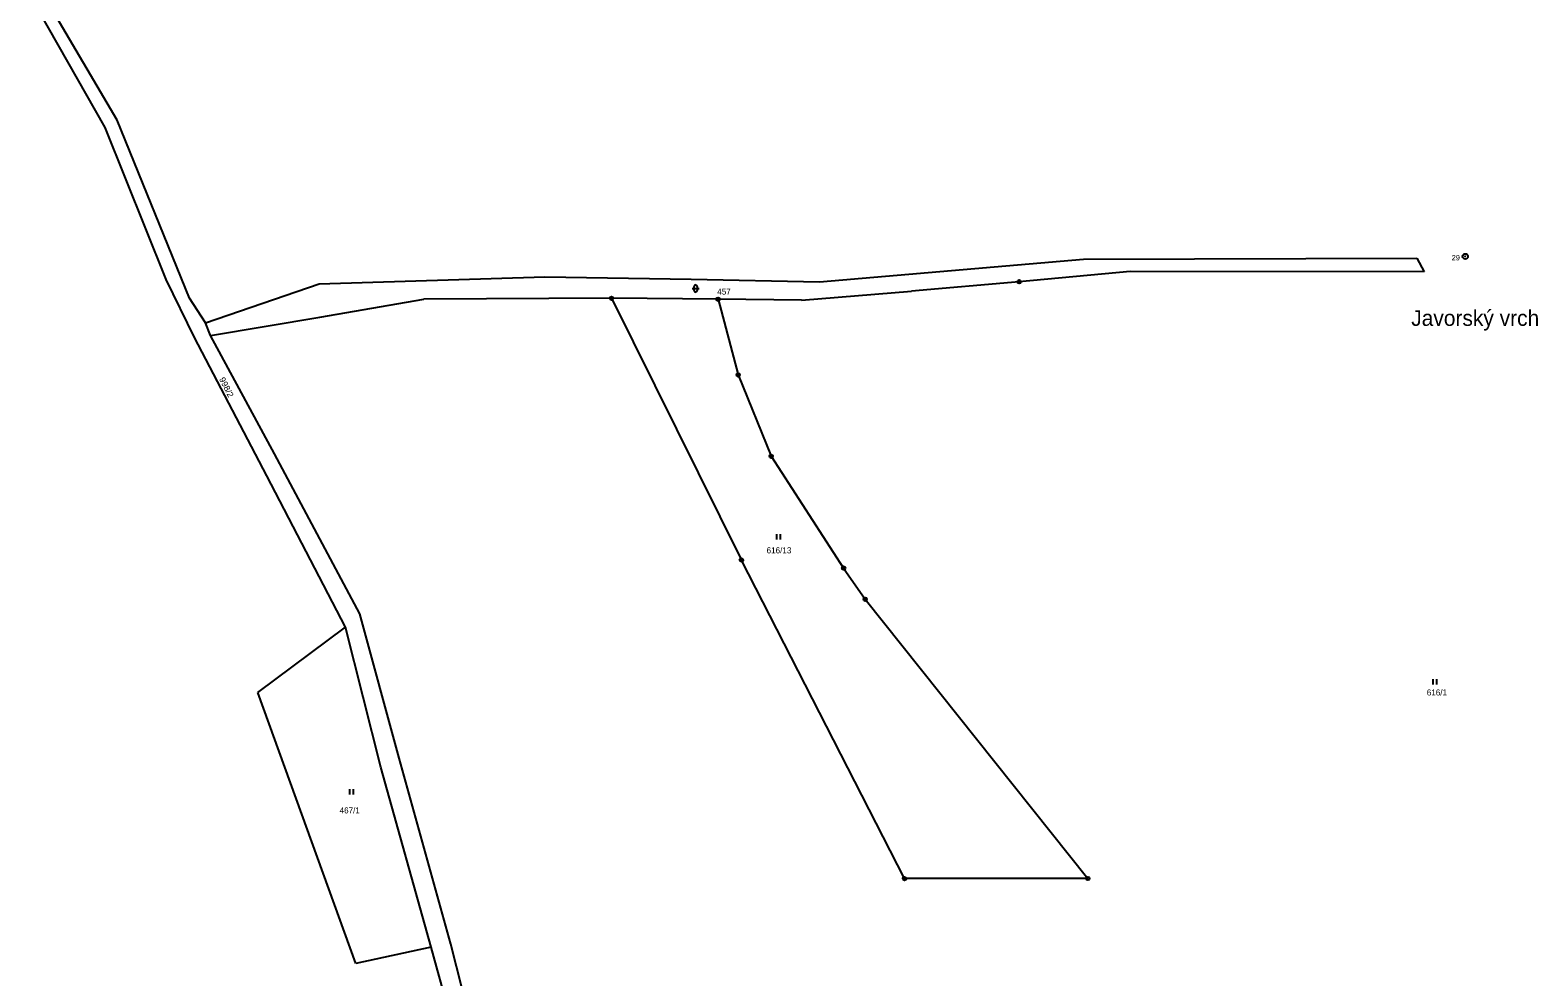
# Model space of a CAD drawing. Extents: x -754970 to -752637, y -970569 to -968179.
# Drawn here: x -754897.5 to -754473.8, y -969234.1 to -968968.3 of the extents above; entities that cross this region are included whole.
import ezdxf
from ezdxf.enums import TextEntityAlignment as Align

# ---------------------------------------------------------------- set-up
doc = ezdxf.new("R2010")
doc.units = 0
doc.header["$LTSCALE"] = 0.68
for name, color, linetype, lineweight in [('1', 7, 'Continuous', 25), ('3', 7, 'Continuous', 25), ('7', 7, 'Continuous', 13), ('8', 7, 'Continuous', 25)]:
    doc.layers.add(name, color=color, linetype=linetype, lineweight=lineweight)
doc.layers.add('2', color=7, linetype='Continuous')

msp = doc.modelspace()

# ---------------------------------------------------------------- linework, layer by layer
at = {"layer": '1'}
for p, q in [((-754876.46, -968995.58), (-754897.5, -968958.43)), ((-754873.07, -968993.57), (-754892.08, -968961.21)), ((-754852.68, -969043.52), (-754873.07, -968993.57)), ((-754859.28, -969038.29), (-754876.46, -968995.58)), ((-754601.47, -969032.61), (-754507.79, -969032.31)), ((-754507.79, -969032.31), (-754505.73, -969036.16)), ((-754675.7, -969038.93), (-754601.47, -969032.61)), ((-754588.39, -969035.99), (-754619.57, -969038.92)), ((-754505.73, -969036.16), (-754588.39, -969035.99)), ((-754851.31, -969054.58), (-754859.28, -969038.29)), ((-754848.25, -969050.43), (-754816.28, -969039.5)), ((-754816.28, -969039.5), (-754752.89, -969037.51)), ((-754752.89, -969037.51), (-754711.78, -969038.17)), ((-754711.78, -969038.17), (-754675.7, -969038.93)), ((-754619.57, -969038.92), (-754649.88, -969041.54)), ((-754848.25, -969050.43), (-754852.68, -969043.52)), ((-754816.13, -969048.84), (-754786.87, -969043.85)), ((-754734.15, -969043.55), (-754786.87, -969043.85)), ((-754734.15, -969043.55), (-754697.63, -969117.06)), ((-754704.19, -969043.83), (-754734.15, -969043.55)), ((-754704.19, -969043.83), (-754698.54, -969065.07)), ((-754680.73, -969044.05), (-754704.19, -969043.83)), ((-754680.73, -969044.05), (-754649.88, -969041.54)), ((-754846.85, -969053.96), (-754816.13, -969048.84)), ((-754846.85, -969053.96), (-754848.25, -969050.43)), ((-754830.95, -969093.37), (-754851.31, -969054.58)), ((-754828.8, -969087.27), (-754846.85, -969053.96)), ((-754698.54, -969065.07), (-754689.26, -969087.93)), ((-754804.82, -969132.17), (-754828.8, -969087.27)), ((-754689.26, -969087.93), (-754668.91, -969119.32)), ((-754808.89, -969135.86), (-754830.95, -969093.37)), ((-754651.78, -969206.52), (-754697.63, -969117.06)), ((-754668.91, -969119.32), (-754662.85, -969128.06)), ((-754662.85, -969128.06), (-754600.28, -969206.48)), ((-754793.77, -969172.72), (-754804.82, -969132.17)), ((-754833.49, -969154.29), (-754808.89, -969135.86)), ((-754799, -969175.19), (-754808.89, -969135.86)), ((-754805.95, -969230.31), (-754833.49, -969154.29)), ((-754784.8, -969225.72), (-754799, -969175.19)), ((-754779.32, -969224.89), (-754793.77, -969172.72)), ((-754600.28, -969206.48), (-754651.78, -969206.52)), ((-754784.8, -969225.72), (-754805.95, -969230.31)), ((-754767.23, -969289.83), (-754784.8, -969225.72)), ((-754762.79, -969290.01), (-754779.32, -969224.89))]:
    msp.add_line(p, q, dxfattribs=at)
at = {"layer": '3'}
for p, q in [((-754711.471, -969040.801), (-754709.469, -969040.801)), ((-754710.971, -969040.301), (-754710.971, -969041.302)), ((-754709.969, -969041.302), (-754709.969, -969040.301)), ((-754687.671, -969111.27), (-754687.671, -969109.77)), ((-754686.67, -969111.27), (-754686.67, -969109.77)), ((-754503.221, -969151.99), (-754503.221, -969150.49)), ((-754502.22, -969151.99), (-754502.22, -969150.49)), ((-754807.641, -969182.89), (-754807.641, -969181.39)), ((-754806.64, -969182.89), (-754806.64, -969181.39))]:
    msp.add_line(p, q, dxfattribs=at)
for centre, start, end in [((-754710.47, -969040.3009), 0, 180), ((-754710.47, -969041.3009), 180, 359.98789)]:
    msp.add_arc(centre, 0.5, start, end, dxfattribs=at)
at = {"layer": '8'}
for centre, radius in [((-754494.23, -969031.7898), 0.75), ((-754494.23, -969031.7898), 0.03), ((-754619.57, -969038.9199), 0.5), ((-754619.57, -969038.9199), 0.0303), ((-754734.15, -969043.5499), 0.5), ((-754734.15, -969043.5499), 0.0303), ((-754704.19, -969043.8299), 0.5), ((-754704.19, -969043.8299), 0.0303), ((-754698.54, -969065.0699), 0.5), ((-754698.54, -969065.0699), 0.0303), ((-754689.26, -969087.9299), 0.5), ((-754689.26, -969087.9299), 0.0303), ((-754697.63, -969117.0599), 0.5), ((-754697.63, -969117.0599), 0.0303), ((-754668.91, -969119.3199), 0.5), ((-754668.91, -969119.3199), 0.0303), ((-754662.85, -969128.0599), 0.5), ((-754662.85, -969128.0599), 0.0303), ((-754651.78, -969206.5199), 0.5), ((-754600.28, -969206.4799), 0.5), ((-754651.78, -969206.5199), 0.0303), ((-754600.28, -969206.4799), 0.0303)]:
    msp.add_circle(centre, radius, dxfattribs=at)

# ---------------------------------------------------------------- texts
at = {"layer": '2'}
for s, p in [('457', (-754702.519, -969042.515)), ('616/13', (-754687.07, -969115.175)), ('616/1', (-754502.19, -969155.085)), ('467/1', (-754807.7, -969188.205))]:
    msp.add_text(s, height=1.7, dxfattribs=at).set_placement(p, align=Align.CENTER)
at = {"layer": '2', "width": 1.05}
msp.add_text('998/2', height=1.7, rotation=297, dxfattribs=at).set_placement((-754843.0883, -969068.9186), align=Align.CENTER)
at = {"layer": '7'}
msp.add_text('Javorský vrch', height=4.4, dxfattribs=at).set_placement((-754491.429, -969051.3), align=Align.CENTER)
at = {"layer": '8'}
msp.add_text('29', height=1.5, dxfattribs=at).set_placement((-754495.729, -969032.907), align=Align.RIGHT)

doc.saveas('drawing.dxf')
